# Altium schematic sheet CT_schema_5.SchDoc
size 247 x 146 mm
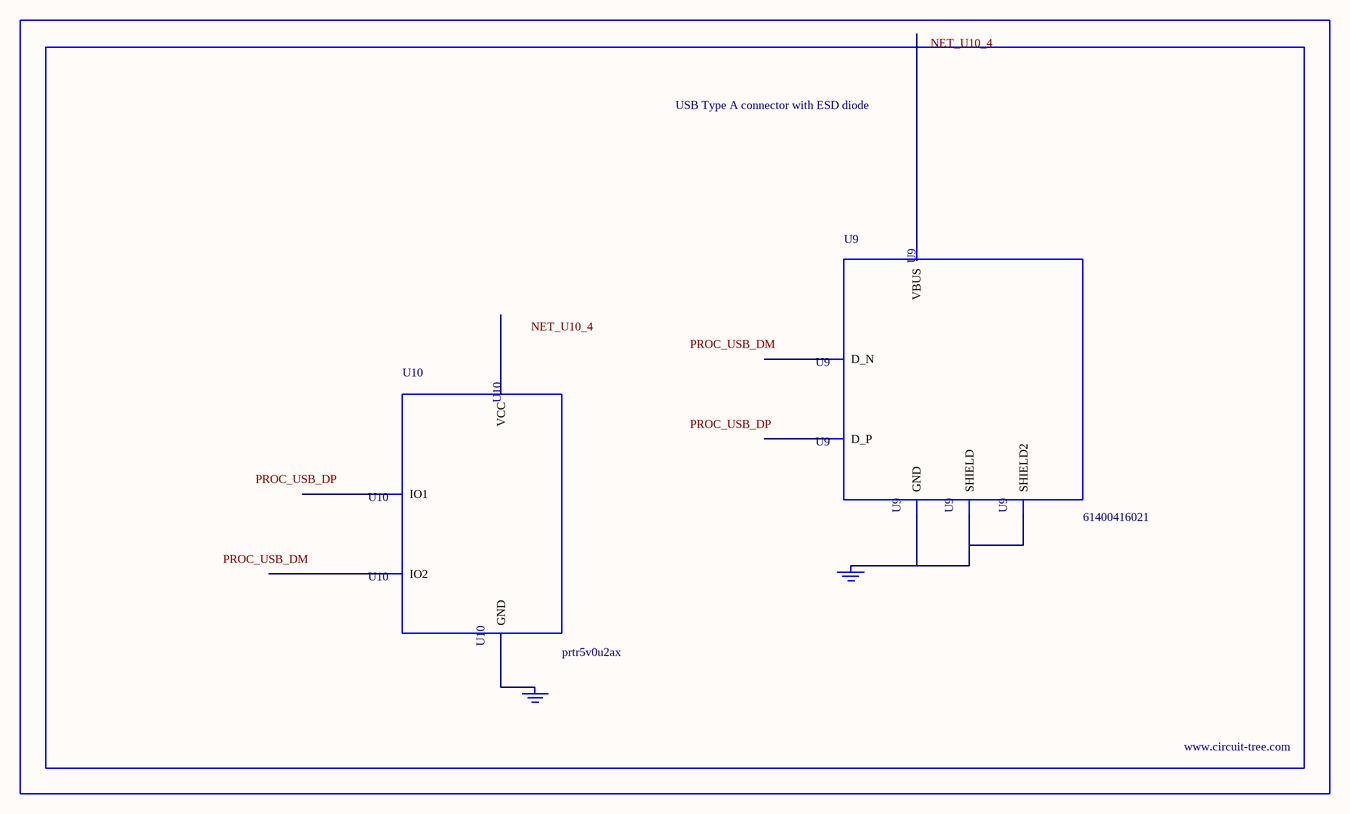
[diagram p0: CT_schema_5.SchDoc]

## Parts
BORDER4  (no value)
GND_INSTANCE_4_0  (no value)
GND_INSTANCE_4_1  (no value)
U9  61400416021  [USB-A-H]
U10  prtr5v0u2ax  [SOT143B]

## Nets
NetGND_INSTANCE_4_0_0: GND_INSTANCE_4_0.0(GND) U9.4(GND) U9.5(SHIELD) U9.6(SHIELD2)
NetGND_INSTANCE_4_1_0: GND_INSTANCE_4_1.0(GND) U10.1(GND)

Not connected (* = marked no-connect by the designer): U9 1(VBUS) 2(D_N) 3(D_P); U10 2(IO1) 3(IO2) 4(VCC)

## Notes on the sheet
- Labels drawn without touching a wire or pin: NET_U10_4, PROC_USB_DM, PROC_USB_DP

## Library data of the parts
BORDER4 = BORDER_PAGE4
GND_INSTANCE_4_0 GND_INSTANCE_4_1 = GND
